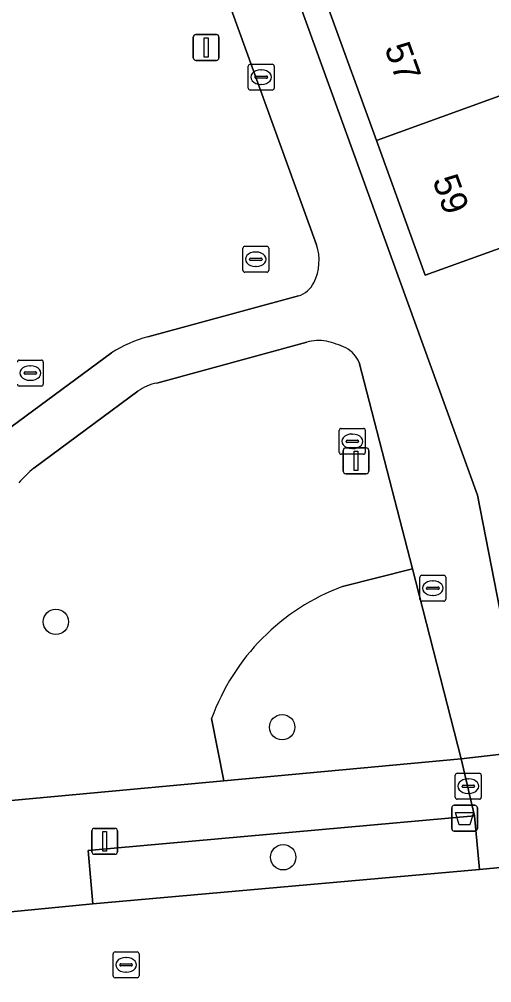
# Model space of a CAD drawing. Extents: x 160377 to 161131, y 383938 to 384853.
# Drawn here: x 160663.39 to 160681.61, y 384498.34 to 384535.5 of the extents above; entities that cross this region are included whole.
import ezdxf

# ---------------------------------------------------------------- set-up
doc = ezdxf.new("R2010")
doc.units = 0
for name, color, linetype in [('IMGEO_Afvalbak', 7, 'Continuous'), ('IMGEO_Boom', 7, 'Continuous'), ('IMGEO_Brandkraan', 7, 'Continuous'), ('IMGEO_Erf', 7, 'Continuous'), ('IMGEO_Groenvoorziening', 7, 'Continuous'), ('IMGEO_Kolk', 7, 'Continuous'), ('IMGEO_Lichtmast', 7, 'Continuous'), ('IMGEO_Pand', 7, 'Continuous'), ('IMGEO_Pand_nummerreeks', 7, 'Continuous'), ('IMGEO_Rijbaan_lokaal_open', 7, 'Continuous'), ('IMGEO_Rioolput', 7, 'Continuous'), ('IMGEO_Voetgangersgebied_open', 7, 'Continuous'), ('IMGEO_Voetpad_open', 7, 'Continuous')]:
    doc.layers.add(name, color=color, linetype=linetype)

msp = doc.modelspace()

# ---------------------------------------------------------------- linework, layer by layer
at = {"layer": 'IMGEO_Afvalbak'}
for p, q in [((160680.166, 384505.187), (160680.956, 384505.187)), ((160680.956, 384505.187), (160680.166, 384505.187)), ((160680.066, 384504.287), (160680.066, 384505.087)), ((160680.066, 384505.087), (160680.066, 384504.287)), ((160681.056, 384505.087), (160681.056, 384504.287)), ((160681.056, 384504.287), (160681.056, 384505.087)), ((160680.956, 384504.187), (160680.166, 384504.187)), ((160680.166, 384504.187), (160680.956, 384504.187))]:
    msp.add_line(p, q, dxfattribs=at)
msp.add_lwpolyline([(160680.209, 384504.901), (160680.913, 384504.901), (160680.764, 384504.431), (160680.358, 384504.431), (160680.209, 384504.901)], dxfattribs=at)
for centre, start, end in [((160680.166, 384505.087), 90, 180), ((160680.166, 384505.087), 90, 180), ((160680.956, 384505.087), 0, 90), ((160680.956, 384505.087), 360, 90), ((160680.166, 384504.287), 180, 270), ((160680.166, 384504.287), 180, 270), ((160680.956, 384504.287), 270, 0), ((160680.956, 384504.287), 270, 0)]:
    msp.add_arc(centre, 0.1, start, end, dxfattribs=at)
at = {"layer": 'IMGEO_Boom'}
for centre in [(160664.797, 384512.261), (160673.527, 384508.196), (160673.567, 384503.181)]:
    msp.add_circle(centre, 0.489, dxfattribs=at)
at = {"layer": 'IMGEO_Brandkraan'}
for p, q in [((160680.206, 384505.495), (160680.206, 384506.347)), ((160680.281, 384506.421), (160681.133, 384506.421)), ((160681.207, 384506.347), (160681.207, 384505.495)), ((160680.465, 384505.915), (160680.465, 384505.927)), ((160680.508, 384505.964), (160680.906, 384505.964)), ((160680.694, 384506.201), (160680.719, 384506.201)), ((160680.949, 384505.927), (160680.949, 384505.915)), ((160680.903, 384505.878), (160680.505, 384505.878)), ((160680.717, 384505.641), (160680.692, 384505.641)), ((160681.133, 384505.421), (160680.281, 384505.421))]:
    msp.add_line(p, q, dxfattribs=at)
for points in [[(160680.206, 384505.495), (160680.206, 384506.347)], [(160680.281, 384506.421), (160681.133, 384506.421)], [(160681.207, 384506.347), (160681.207, 384505.495)], [(160681.133, 384505.421), (160680.281, 384505.421)]]:
    msp.add_lwpolyline(points, dxfattribs=at)
for centre, radius, start, end in [((160680.283, 384506.345), 0.0765, 91.552, 178.448), ((160680.283, 384506.345), 0.0765, 91.552, 178.448), ((160681.131, 384506.345), 0.0765, 1.552, 88.448), ((160681.131, 384506.345), 0.0765, 1.552, 88.448), ((160680.505, 384505.924), 0.0403, 85.8775, 175.7526), ((160680.502, 384505.914), 0.0366, 178.938, 274.7102), ((160680.906, 384505.921), 0.043, 264.8664, 352.4533), ((160680.91, 384505.926), 0.0386, 1.7309, 96.639), ((160680.283, 384505.497), 0.0765, 181.552, 268.448), ((160680.283, 384505.497), 0.0765, 181.552, 268.448), ((160681.131, 384505.497), 0.0765, 271.552, 358.448), ((160681.131, 384505.497), 0.0765, 271.552, 358.448)]:
    msp.add_arc(centre, radius, start, end, dxfattribs=at)
for centre, major_axis, ratio, start_param, end_param in [((160680.693, 384505.921), (-0.387, 0.002), 0.722429, 4.712389, 7.853982), ((160680.718, 384505.921), (-0.39, 0.002), 0.717154, 1.570796, 4.712389)]:
    msp.add_ellipse(centre, major_axis=major_axis, ratio=ratio, start_param=start_param, end_param=end_param, dxfattribs=at)
at = {"layer": 'IMGEO_Erf'}
for points in [[(160742.043, 384557.929), (160741.675, 384559.771), (160712.316, 384578.736), (160711.06, 384579.547), (160690.284, 384592.968), (160678.608, 384600.475), (160670.645, 384605.594), (160652.047, 384589.687), (160648.865, 384586.974), (160652.625, 384581.692), (160662.829, 384567.417), (160665.29, 384560.709), (160670.064, 384547.52), (160670.583, 384546.086), (160681.057, 384517.15), (160682.984, 384507.279), (160717.593, 384514.044), (160723.481, 384515.195), (160749.399, 384520.262)], [(160683.874, 384539.137), (160685.758, 384533.937), (160687.643, 384528.737), (160679.045, 384525.635), (160677.165, 384530.822), (160675.28, 384536.022), (160673.396, 384541.222), (160671.511, 384546.422), (160680.104, 384549.537), (160681.989, 384544.337)]]:
    msp.add_lwpolyline(points, close=True, dxfattribs=at)
at = {"layer": 'IMGEO_Groenvoorziening'}
for points in [[(160674.853, 384526.804), (160665.84, 384551.711), (160663.489, 384553.259), (160662.566, 384554.598), (160660.752, 384558.915), (160658.847, 384561.034), (160657.157, 384563.866), (160657.46, 384566.101)], [(160668.343, 384523.255), (160674.153, 384524.83)], [(160674.478, 384523.05), (160668.689, 384521.472)], [(160662.813, 384519.592), (160666.946, 384522.637)], [(160675.854, 384513.619), (160678.548, 384514.302), (160676.497, 384522.259)], [(160667.964, 384521.156), (160663.95, 384518.188)], [(160670.803, 384508.527), (160671.275, 384506.125), (160680.437, 384506.971), (160678.548, 384514.302)], [(160678.548, 384514.302), (160675.854, 384513.619)], [(160659.653, 384512.586), (160660.286, 384505.11), (160671.275, 384506.125), (160670.803, 384508.527)]]:
    msp.add_lwpolyline(points, dxfattribs=at)
msp.add_lwpolyline([(160680.951, 384504.783), (160666.045, 384503.439), (160666.223, 384501.382), (160681.144, 384502.714)], close=True, dxfattribs=at)
for centre, radius, start, end in [((160673.034, 384526.198), 1.917, 333.5, 18.4402), ((160673.817, 384525.826), 1.051, 288.639, 332.5952), ((160669.635, 384518.445), 4.98, 105.0415, 122.6855), ((160674.956, 384521.151), 1.958, 81.9393, 104.1422), ((160674.217, 384518.988), 4.225, 65.2077, 76.1179), ((160675.524, 384521.895), 1.038, 20.5003, 63.4181), ((160669.043, 384519.671), 1.836, 101.1093, 125.9918), ((160667.261, 384514.216), 5.171, 129.8121, 138.7857), ((160678.81, 384505.636), 8.513, 110.3165, 160.1467), ((160678.81, 384505.636), 8.513, 110.3165, 160.1467)]:
    msp.add_arc(centre, radius, start, end, dxfattribs=at)
at = {"layer": 'IMGEO_Kolk'}
for p, q in [((160672.217, 384532.844), (160672.217, 384533.696)), ((160672.292, 384533.77), (160673.144, 384533.77)), ((160672.705, 384533.55), (160672.73, 384533.55)), ((160673.218, 384533.696), (160673.218, 384532.844)), ((160672.476, 384533.264), (160672.476, 384533.276)), ((160672.914, 384533.227), (160672.516, 384533.227)), ((160672.519, 384533.313), (160672.917, 384533.313)), ((160672.96, 384533.276), (160672.96, 384533.264)), ((160673.144, 384532.77), (160672.292, 384532.77)), ((160672.728, 384532.99), (160672.703, 384532.99)), ((160678.838, 384513.132), (160678.838, 384513.984)), ((160678.913, 384514.058), (160679.765, 384514.058)), ((160679.326, 384513.838), (160679.351, 384513.838)), ((160679.839, 384513.984), (160679.839, 384513.132)), ((160679.097, 384513.552), (160679.097, 384513.564)), ((160679.535, 384513.515), (160679.137, 384513.515)), ((160679.14, 384513.601), (160679.538, 384513.601)), ((160679.581, 384513.564), (160679.581, 384513.552)), ((160679.765, 384513.058), (160678.913, 384513.058)), ((160679.349, 384513.278), (160679.324, 384513.278))]:
    msp.add_line(p, q, dxfattribs=at)
for points in [[(160672.217, 384532.844), (160672.217, 384533.696)], [(160672.292, 384533.77), (160673.144, 384533.77)], [(160673.218, 384533.696), (160673.218, 384532.844)], [(160673.144, 384532.77), (160672.292, 384532.77)], [(160678.838, 384513.132), (160678.838, 384513.984)], [(160678.913, 384514.058), (160679.765, 384514.058)], [(160679.839, 384513.984), (160679.839, 384513.132)], [(160679.765, 384513.058), (160678.913, 384513.058)]]:
    msp.add_lwpolyline(points, dxfattribs=at)
for centre, radius, start, end in [((160672.294, 384533.694), 0.0765, 91.552, 178.448), ((160672.294, 384533.694), 0.0765, 91.552, 178.448), ((160673.142, 384533.694), 0.0765, 1.552, 88.448), ((160673.142, 384533.694), 0.0765, 1.552, 88.448), ((160672.516, 384533.273), 0.0403, 85.8775, 175.7526), ((160672.513, 384533.263), 0.0366, 178.938, 274.7102), ((160672.917, 384533.27), 0.043, 264.8664, 352.4533), ((160672.921, 384533.275), 0.0386, 1.7309, 96.639), ((160672.294, 384532.846), 0.0765, 181.552, 268.448), ((160672.294, 384532.846), 0.0765, 181.552, 268.448), ((160673.142, 384532.846), 0.0765, 271.552, 358.448), ((160673.142, 384532.846), 0.0765, 271.552, 358.448), ((160678.915, 384513.982), 0.0765, 91.552, 178.448), ((160678.915, 384513.982), 0.0765, 91.552, 178.448), ((160679.763, 384513.982), 0.0765, 1.552, 88.448), ((160679.763, 384513.982), 0.0765, 1.552, 88.448), ((160679.137, 384513.561), 0.0403, 85.8775, 175.7526), ((160679.134, 384513.551), 0.0366, 178.938, 274.7102), ((160679.538, 384513.558), 0.043, 264.8664, 352.4533), ((160679.542, 384513.563), 0.0386, 1.7309, 96.639), ((160678.915, 384513.134), 0.0765, 181.552, 268.448), ((160678.915, 384513.134), 0.0765, 181.552, 268.448), ((160679.763, 384513.134), 0.0765, 271.552, 358.448), ((160679.763, 384513.134), 0.0765, 271.552, 358.448)]:
    msp.add_arc(centre, radius, start, end, dxfattribs=at)
for centre, major_axis, ratio, start_param, end_param in [((160672.704, 384533.27), (-0.387, 0.002), 0.722429, 4.712389, 7.853982), ((160672.729, 384533.27), (-0.39, 0.002), 0.717154, 1.570796, 4.712389), ((160679.325, 384513.558), (-0.387, 0.002), 0.722429, 4.712389, 7.853982), ((160679.35, 384513.558), (-0.39, 0.002), 0.717154, 1.570796, 4.712389)]:
    msp.add_ellipse(centre, major_axis=major_axis, ratio=ratio, start_param=start_param, end_param=end_param, dxfattribs=at)
at = {"layer": 'IMGEO_Lichtmast'}
for p, q in [((160670.199, 384534.915), (160670.989, 384534.915)), ((160670.989, 384534.915), (160670.199, 384534.915)), ((160670.099, 384534.015), (160670.099, 384534.815)), ((160670.099, 384534.815), (160670.099, 384534.015)), ((160671.089, 384534.815), (160671.089, 384534.015)), ((160671.089, 384534.015), (160671.089, 384534.815)), ((160670.989, 384533.915), (160670.199, 384533.915)), ((160670.199, 384533.915), (160670.989, 384533.915)), ((160675.979, 384518.973), (160676.769, 384518.973)), ((160676.769, 384518.973), (160675.979, 384518.973)), ((160675.879, 384518.073), (160675.879, 384518.873)), ((160675.879, 384518.873), (160675.879, 384518.073)), ((160676.869, 384518.873), (160676.869, 384518.073)), ((160676.869, 384518.073), (160676.869, 384518.873)), ((160676.769, 384517.973), (160675.979, 384517.973)), ((160675.979, 384517.973), (160676.769, 384517.973)), ((160666.185, 384503.396), (160666.185, 384504.196)), ((160666.185, 384504.196), (160666.185, 384503.396)), ((160666.285, 384504.296), (160667.075, 384504.296)), ((160667.075, 384504.296), (160666.285, 384504.296)), ((160667.175, 384504.196), (160667.175, 384503.396)), ((160667.175, 384503.396), (160667.175, 384504.196)), ((160667.075, 384503.296), (160666.285, 384503.296)), ((160666.285, 384503.296), (160667.075, 384503.296))]:
    msp.add_line(p, q, dxfattribs=at)
for points in [[(160670.519, 384534.79), (160670.669, 384534.79), (160670.669, 384534.04), (160670.519, 384534.04), (160670.519, 384534.79)], [(160676.299, 384518.848), (160676.449, 384518.848), (160676.449, 384518.098), (160676.299, 384518.098), (160676.299, 384518.848)], [(160666.605, 384504.171), (160666.755, 384504.171), (160666.755, 384503.421), (160666.605, 384503.421), (160666.605, 384504.171)]]:
    msp.add_lwpolyline(points, dxfattribs=at)
for centre, start, end in [((160670.199, 384534.815), 90, 180), ((160670.199, 384534.815), 90, 180), ((160670.989, 384534.815), 0, 90), ((160670.989, 384534.815), 360, 90), ((160670.199, 384534.015), 180, 270), ((160670.199, 384534.015), 180, 270), ((160670.989, 384534.015), 270, 0), ((160670.989, 384534.015), 270, 0), ((160675.979, 384518.873), 90, 180), ((160675.979, 384518.873), 90, 180), ((160676.769, 384518.873), 0, 90), ((160676.769, 384518.873), 360, 90), ((160675.979, 384518.073), 180, 270), ((160675.979, 384518.073), 180, 270), ((160676.769, 384518.073), 270, 0), ((160676.769, 384518.073), 270, 0), ((160666.285, 384504.196), 90, 180), ((160666.285, 384504.196), 90, 180), ((160667.075, 384504.196), 0, 90), ((160667.075, 384504.196), 360, 90), ((160666.285, 384503.396), 180, 270), ((160666.285, 384503.396), 180, 270), ((160667.075, 384503.396), 270, 0), ((160667.075, 384503.396), 270, 0)]:
    msp.add_arc(centre, 0.1, start, end, dxfattribs=at)
at = {"layer": 'IMGEO_Pand'}
for points in [[(160683.874, 384539.137), (160675.28, 384536.022), (160677.165, 384530.822), (160685.758, 384533.937)], [(160685.758, 384533.937), (160677.165, 384530.822), (160679.045, 384525.635), (160687.643, 384528.737)]]:
    msp.add_lwpolyline(points, close=True, dxfattribs=at)
at = {"layer": 'IMGEO_Rijbaan_lokaal_open'}
msp.add_lwpolyline([(160681.08, 384497.44), (160684.957, 384497.974), (160686.513, 384498.219), (160686.58, 384498.232), (160685.714, 384503.375), (160683.364, 384502.943), (160682.351, 384502.826), (160681.144, 384502.714), (160666.223, 384501.382), (160656.868, 384500.475), (160656.011, 384500.414), (160656.518, 384494.884), (160658.107, 384495.062), (160660.061, 384495.216)], dxfattribs=at)
at = {"layer": 'IMGEO_Rioolput'}
for p, q in [((160672.085, 384526.746), (160672.937, 384526.746)), ((160672.01, 384525.82), (160672.01, 384526.672)), ((160672.498, 384526.526), (160672.523, 384526.526)), ((160673.011, 384526.672), (160673.011, 384525.82)), ((160672.269, 384526.24), (160672.269, 384526.252)), ((160672.707, 384526.203), (160672.309, 384526.203)), ((160672.312, 384526.289), (160672.71, 384526.289)), ((160672.753, 384526.252), (160672.753, 384526.24)), ((160672.937, 384525.746), (160672.085, 384525.746)), ((160672.521, 384525.966), (160672.496, 384525.966)), ((160663.386, 384522.356), (160664.238, 384522.356)), ((160664.312, 384522.282), (160664.312, 384521.43)), ((160663.613, 384521.899), (160664.011, 384521.899)), ((160663.799, 384522.136), (160663.824, 384522.136)), ((160663.57, 384521.85), (160663.57, 384521.862)), ((160664.008, 384521.813), (160663.61, 384521.813)), ((160663.822, 384521.576), (160663.797, 384521.576)), ((160664.054, 384521.862), (160664.054, 384521.85)), ((160664.238, 384521.356), (160663.386, 384521.356)), ((160675.807, 384519.723), (160676.659, 384519.723)), ((160675.732, 384518.797), (160675.732, 384519.649)), ((160676.22, 384519.503), (160676.245, 384519.503)), ((160676.733, 384519.649), (160676.733, 384518.797)), ((160675.991, 384519.217), (160675.991, 384519.229)), ((160676.429, 384519.18), (160676.031, 384519.18)), ((160676.034, 384519.266), (160676.432, 384519.266)), ((160676.243, 384518.943), (160676.218, 384518.943)), ((160676.475, 384519.229), (160676.475, 384519.217)), ((160676.659, 384518.723), (160675.807, 384518.723)), ((160667.005, 384498.606), (160667.005, 384499.458)), ((160667.08, 384499.532), (160667.932, 384499.532)), ((160667.493, 384499.312), (160667.518, 384499.312)), ((160668.006, 384499.458), (160668.006, 384498.606)), ((160667.264, 384499.026), (160667.264, 384499.038)), ((160667.702, 384498.989), (160667.304, 384498.989)), ((160667.307, 384499.075), (160667.705, 384499.075)), ((160667.748, 384499.038), (160667.748, 384499.026)), ((160667.932, 384498.532), (160667.08, 384498.532)), ((160667.516, 384498.752), (160667.491, 384498.752))]:
    msp.add_line(p, q, dxfattribs=at)
for points in [[(160672.085, 384526.746), (160672.937, 384526.746)], [(160672.01, 384525.82), (160672.01, 384526.672)], [(160673.011, 384526.672), (160673.011, 384525.82)], [(160672.937, 384525.746), (160672.085, 384525.746)], [(160663.386, 384522.356), (160664.238, 384522.356)], [(160664.312, 384522.282), (160664.312, 384521.43)], [(160664.238, 384521.356), (160663.386, 384521.356)], [(160675.807, 384519.723), (160676.659, 384519.723)], [(160675.732, 384518.797), (160675.732, 384519.649)], [(160676.733, 384519.649), (160676.733, 384518.797)], [(160676.659, 384518.723), (160675.807, 384518.723)], [(160667.005, 384498.606), (160667.005, 384499.458)], [(160667.08, 384499.532), (160667.932, 384499.532)], [(160668.006, 384499.458), (160668.006, 384498.606)], [(160667.932, 384498.532), (160667.08, 384498.532)]]:
    msp.add_lwpolyline(points, dxfattribs=at)
for centre, radius, start, end in [((160672.087, 384526.67), 0.0765, 91.552, 178.448), ((160672.087, 384526.67), 0.0765, 91.552, 178.448), ((160672.935, 384526.67), 0.0765, 1.552, 88.448), ((160672.935, 384526.67), 0.0765, 1.552, 88.448), ((160672.309, 384526.249), 0.0403, 85.8775, 175.7526), ((160672.306, 384526.239), 0.0366, 178.938, 274.7102), ((160672.71, 384526.246), 0.043, 264.8664, 352.4533), ((160672.714, 384526.251), 0.0386, 1.7309, 96.639), ((160672.087, 384525.822), 0.0765, 181.552, 268.448), ((160672.087, 384525.822), 0.0765, 181.552, 268.448), ((160672.935, 384525.822), 0.0765, 271.552, 358.448), ((160672.935, 384525.822), 0.0765, 271.552, 358.448), ((160663.388, 384522.28), 0.0765, 91.552, 178.448), ((160663.388, 384522.28), 0.0765, 91.552, 178.448), ((160664.236, 384522.28), 0.0765, 1.552, 88.448), ((160664.236, 384522.28), 0.0765, 1.552, 88.448), ((160663.61, 384521.859), 0.0403, 85.8775, 175.7526), ((160664.015, 384521.861), 0.0386, 1.7309, 96.639), ((160663.607, 384521.849), 0.0366, 178.938, 274.7102), ((160664.011, 384521.856), 0.043, 264.8664, 352.4533), ((160663.388, 384521.432), 0.0765, 181.552, 268.448), ((160663.388, 384521.432), 0.0765, 181.552, 268.448), ((160664.236, 384521.432), 0.0765, 271.552, 358.448), ((160664.236, 384521.432), 0.0765, 271.552, 358.448), ((160675.809, 384519.647), 0.0765, 91.552, 178.448), ((160675.809, 384519.647), 0.0765, 91.552, 178.448), ((160676.657, 384519.647), 0.0765, 1.552, 88.448), ((160676.657, 384519.647), 0.0765, 1.552, 88.448), ((160676.031, 384519.226), 0.0403, 85.8775, 175.7526), ((160676.028, 384519.216), 0.0366, 178.938, 274.7102), ((160676.432, 384519.223), 0.043, 264.8664, 352.4533), ((160676.436, 384519.228), 0.0386, 1.7309, 96.639), ((160675.809, 384518.799), 0.0765, 181.552, 268.448), ((160675.809, 384518.799), 0.0765, 181.552, 268.448), ((160676.657, 384518.799), 0.0765, 271.552, 358.448), ((160676.657, 384518.799), 0.0765, 271.552, 358.448), ((160667.082, 384499.456), 0.0765, 91.552, 178.448), ((160667.082, 384499.456), 0.0765, 91.552, 178.448), ((160667.93, 384499.456), 0.0765, 1.552, 88.448), ((160667.93, 384499.456), 0.0765, 1.552, 88.448), ((160667.304, 384499.035), 0.0403, 85.8775, 175.7526), ((160667.301, 384499.025), 0.0366, 178.938, 274.7102), ((160667.705, 384499.032), 0.043, 264.8664, 352.4533), ((160667.709, 384499.037), 0.0386, 1.7309, 96.639), ((160667.082, 384498.608), 0.0765, 181.552, 268.448), ((160667.082, 384498.608), 0.0765, 181.552, 268.448), ((160667.93, 384498.608), 0.0765, 271.552, 358.448), ((160667.93, 384498.608), 0.0765, 271.552, 358.448)]:
    msp.add_arc(centre, radius, start, end, dxfattribs=at)
for centre, major_axis, ratio, start_param, end_param in [((160672.497, 384526.246), (-0.387, 0.002), 0.722429, 4.712389, 7.853982), ((160672.522, 384526.246), (-0.39, 0.002), 0.717154, 1.570796, 4.712389), ((160663.798, 384521.856), (-0.387, 0.002), 0.722429, 4.712389, 7.853982), ((160663.823, 384521.856), (-0.39, 0.002), 0.717154, 1.570796, 4.712389), ((160676.219, 384519.223), (-0.387, 0.002), 0.722429, 4.712389, 7.853982), ((160676.244, 384519.223), (-0.39, 0.002), 0.717154, 1.570796, 4.712389), ((160667.492, 384499.032), (-0.387, 0.002), 0.722429, 4.712389, 7.853982), ((160667.517, 384499.032), (-0.39, 0.002), 0.717154, 1.570796, 4.712389)]:
    msp.add_ellipse(centre, major_axis=major_axis, ratio=ratio, start_param=start_param, end_param=end_param, dxfattribs=at)
at = {"layer": 'IMGEO_Voetgangersgebied_open'}
for points in [[(160676.497, 384522.259), (160678.548, 384514.302), (160680.437, 384506.971), (160682.984, 384507.279), (160681.057, 384517.15), (160670.583, 384546.086), (160670.064, 384547.52), (160665.29, 384560.709)], [(160665.84, 384551.711), (160674.853, 384526.804)], [(160674.153, 384524.83), (160668.343, 384523.255)], [(160668.689, 384521.472), (160674.478, 384523.05)], [(160666.946, 384522.637), (160662.813, 384519.592)], [(160663.95, 384518.188), (160667.964, 384521.156)]]:
    msp.add_lwpolyline(points, dxfattribs=at)
for centre, radius, start, end in [((160673.034, 384526.198), 1.917, 333.5, 18.4402), ((160673.817, 384525.826), 1.051, 288.639, 332.5952), ((160669.635, 384518.445), 4.98, 105.0415, 122.6855), ((160674.956, 384521.151), 1.958, 81.9393, 104.1422), ((160674.217, 384518.988), 4.225, 65.2077, 76.1179), ((160675.524, 384521.895), 1.038, 20.5003, 63.4181), ((160669.043, 384519.671), 1.836, 101.1093, 125.9918), ((160667.261, 384514.216), 5.171, 129.8121, 138.7857)]:
    msp.add_arc(centre, radius, start, end, dxfattribs=at)
at = {"layer": 'IMGEO_Voetpad_open'}
for points in [[(160818.393, 384535.428), (160814.707, 384533.039), (160790.946, 384528.391), (160785.079, 384527.244), (160759.828, 384522.305), (160757.353, 384521.841), (160751.078, 384520.595), (160749.399, 384520.262), (160723.481, 384515.195), (160717.593, 384514.044), (160682.984, 384507.279), (160680.437, 384506.971), (160680.951, 384504.783), (160681.144, 384502.714), (160682.351, 384502.826), (160682.165, 384504.852), (160687.745, 384505.957), (160687.9, 384505.71)], [(160653.154, 384502.001), (160653.167, 384502.252), (160656.659, 384502.566), (160656.868, 384500.475), (160666.223, 384501.382), (160666.045, 384503.439), (160680.951, 384504.783), (160680.437, 384506.971), (160671.275, 384506.125), (160660.286, 384505.11), (160656.893, 384504.376), (160656.048, 384504.315), (160614.226, 384500.488), (160610.459, 384499.743)]]:
    msp.add_lwpolyline(points, dxfattribs=at)

# ---------------------------------------------------------------- texts
at = {"layer": 'IMGEO_Pand_nummerreeks'}
for s, p in [('57', (160677.464, 384534.4)), ('59', (160679.314, 384529.295))]:
    msp.add_text(s, height=1, rotation=289.9215, dxfattribs=at).set_placement(p)

doc.saveas('drawing.dxf')
